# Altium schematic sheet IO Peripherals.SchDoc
size A4; DocumentNumber: 6; Revision: B.2(PCB.SCH); SheetNumber: 6; SheetTotal: 6
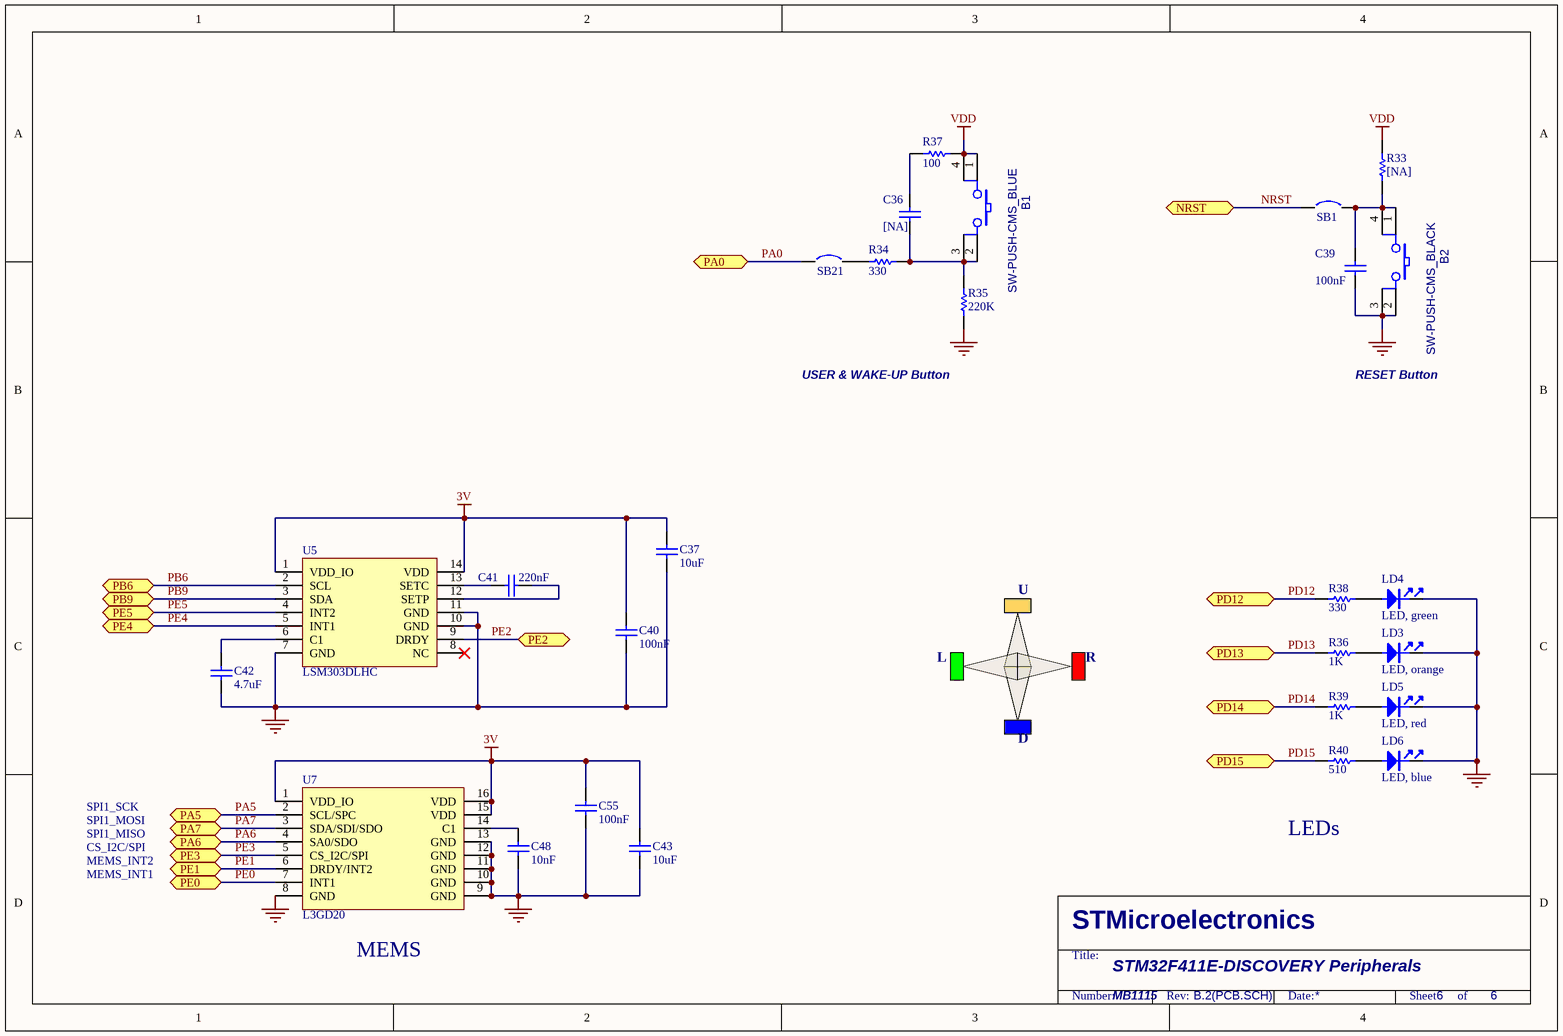
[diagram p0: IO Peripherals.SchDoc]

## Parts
B1  SW-PUSH-CMS_BLUE  [BP1CMS]
B2  SW-PUSH-CMS_BLACK  [BP1CMS]
C36  [NA]  [0402C]
C37  10uF  [0603C]
C39  100nF  [0402C]
C40  100nF  [0402C]
C41  220nF  [0603C]
C42  4.7uF  [0603C]
C43  10uF  [0603C]
C48  10nF  [0603C]
C55  100nF  [0402C]
LD3  LED, orange  [0603D]
LD4  LED, green  [0603D]
LD5  LED, red  [0603D]
LD6  LED, blue  [0603D]
R33  [NA]  [0402R]
R34  330  [0402R]
R35  220K  [0402R]
R36  1K  [0402R]
R37  100  [0402R]
R38  330  [0402R]
R39  1K  [0402R]
R40  510  [0402R]
SB1  Circuit Breaker  [JP2_SMD]  (value not drawn)
SB21  Circuit Breaker  [JP2_SMD]  (value not drawn)
U5  LSM303DLHC  [LGA14(3*5)]
U7  L3GD20  [LGA16-4x4]

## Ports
NRST, PA0, PA5, PA6, PA7, PB6, PB9, PD12, PD13, PD14, PD15, PE0, PE1, PE2, PE3, PE4, PE5

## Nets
3V: C37.2 C40.2 C43.2 C55.2 U5.1(VDD_IO) U5.14(VDD) U7.1(VDD_IO) U7.15(VDD) U7.16(VDD)
GND: B2.2 B2.3 C37.1 C39.1 C40.1 C42.1 C43.1 C48.1 C55.1 LD3.2 LD4.2 LD5.2 LD6.2 R35.1 U5.7(GND) U5.10(GND) U5.11(GND) U7.8(GND) U7.9(GND) U7.10(GND) U7.11(GND) U7.12(GND) U7.13(GND)
VDD: B1.1 B1.4 R33.2 R37.2
NRST: SB1.1 ; port NRST
PA0: SB21.1 ; port PA0
PA5: U7.2(SCL/SPC) ; port PA5
PA6: U7.4(SA0/SDO) ; port PA6
PA7: U7.3(SDA/SDI/SDO) ; port PA7
PB6: U5.2(SCL) ; port PB6
PB9: U5.3(SDA) ; port PB9
PD12: R38.2 ; port PD12
PD13: R36.2 ; port PD13
PD14: R39.2 ; port PD14
PD15: R40.2 ; port PD15
PE0: U7.7(INT1) ; port PE0
PE1: U7.6(DRDY/INT2) ; port PE1
PE2: U5.9(DRDY) ; port PE2
PE3: U7.5(CS_I2C/SPI) ; port PE3
PE4: U5.5(INT1) ; port PE4
PE5: U5.4(INT2) ; port PE5
NetB1_2: B1.2 B1.3 C36.1 R34.2 R35.2
NetB2_1: B2.1 B2.4 C39.2 R33.1 SB1.2
NetC36_2: C36.2 R37.1
NetC41_1: C41.1 U5.13(SETC)
NetC41_2: C41.2 U5.12(SETP)
NetC42_2: C42.2 U5.6(C1)
NetC48_2: C48.2 U7.14(C1)
NetLD3_1: LD3.1 R36.1
NetLD4_1: LD4.1 R38.1
NetLD5_1: LD5.1 R39.1
NetLD6_1: LD6.1 R40.1
NetR34_1: R34.1 SB21.2

Not connected (* = marked no-connect by the designer): U5 8(NC)*

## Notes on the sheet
- USER & WAKE-UP Button
- RESET Button
- U
- L
- R
- D
- SPI1_MOSI
- SPI1_SCK
- SPI1_MISO
- CS_I2C/SPI
- LEDs
- MEMS_INT1
- MEMS_INT2
- (near U7) MEMS
- STM32F411E-DISCOVERY Peripherals
- MB1115

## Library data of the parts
B1 = SW-PUSH-CMS_BLUE: Non-Open Push-Button 0.1A 24V; Manuf_2: FARNELL; Manuf_Part_2: 535-930; Manuf_1: wealthmetal; Manuf_Part_1: TD0341X-G01-BLU; Ref St: 9180120; Description: Non-Open Push Button,Blue 0.1A 24V,Square head,6*6,SMT,180Degree,TD-0341X-GO1,wealthmetal
B2 = SW-PUSH-CMS_BLACK: Non-Open Push-Button 0.1A 24V; Manuf_2: FARNELL; Manuf_Part_2: 535-930; Manuf_1: wealthmetal; Manuf_Part_1: TD0341X-G01-BLA; Ref St: 9180120; Description: Non-Open Push Button,Black 0.1A 24V,Square head,6*6,SMT,180Degree,TD-0341X-GO1,wealthmetal
C36 = Cap_NA_0402: Capacitor,NA,0402; Fitted: NO
C37 C43 = Cap_10uF_X5R_10%_0603: Capacitor,10uF,6.3V,X5R,20%,0603,YAGEO; Manuf_Part_1: CC0603KRX5R5BB106
C39 C40 C55 = Cap_100nF_X7R_10%_0402: Capacitor,100nF,16V,X7R,10%,0402,YAGEO; Manuf_Part_1: CC0402KRX7R7BB104
C41 = Cap_220nF_X7R_10%_0603: Capacitor,220nF,16V,X7R,10%,0603,YAGEO; Manuf_Part_1: CC0603KRX7R7BB224
C42 = Cap_4.7uF_X5R_10%_0603: Capacitor,4.7uF,16V, X5R,10%,0603,YAGEO; Manuf_Part_1: CC0603KRX5R7BB475; Order: CC0603KRX5R7BB105
C48 = Cap_10nF_X7R_10%_0603: Capacitor,10nF,50V,X7R,10%,0603,YAGEO; Manuf_Part_1: CC0603KRX7R9BB103
LD3 = LED_orange: LED, orange, 0603; Manuf_1: everlight; Manuf_Part_1: 19-217/S2C-AM2N2VY/3T; Description: LED,orange,0603,19-217/S2C-AM2N2VY/3T,everlight
LD4 = LED_green: LED, green, 0603; Manuf_1: everlight; Manuf_Part_1: 19-213SYGC/S530-E2/TR8; Description: LED,green,0603,19-213SYGC/S530-E2/TR8,everlight
LD5 = LED_red: LED, red, 0603; Manuf_1: everlight; Manuf_Part_1: 19-213-R6C-AP1Q2B/3T; Description: LED,red,0603,19-213-R6C-AP1Q2B/3T,everlight
LD6 = LED_blue: LED, blue, 0603; Manuf_1: everlight; Manuf_Part_1: 19-217/BHC-ZL1M2RY/3T; Description: LED,Blue,0603,19-217/BHC-ZL1M2RY/3T,everlight
R33 = Res_NA_0402: Resistor,[NA],0402; Fitted: NO
R34 = res1: Resistor
R35 = res1: Resistor; Value: 10K
R36 R39 = Res1: Resistor
R37 = res1: Resistor; Value: 330
R38 R40 = Res1: Resistor; Value: 1K
SB1 SB21 = Circuit Breaker: Solder: YES
U5 = LSM303DLHC: Ultra compact high performance e-compass 3D accelerometer and 3D magnetometer module; Manuf_1: STM; Manuf_Part_1: LSM303DLHCTR; Provided: ST; Ref St: 9177037; ECCN_US/EU: EAR99/NEC
U7 = L3GD20: MEMS motion sensor three-axis digital output gyroscopeelerometer; Manuf_1: STM; Manuf_Part_1: L3GD20TR; Provided: ST; Ref St: 9177042; ECCN_US/EU: EAR99/NEC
